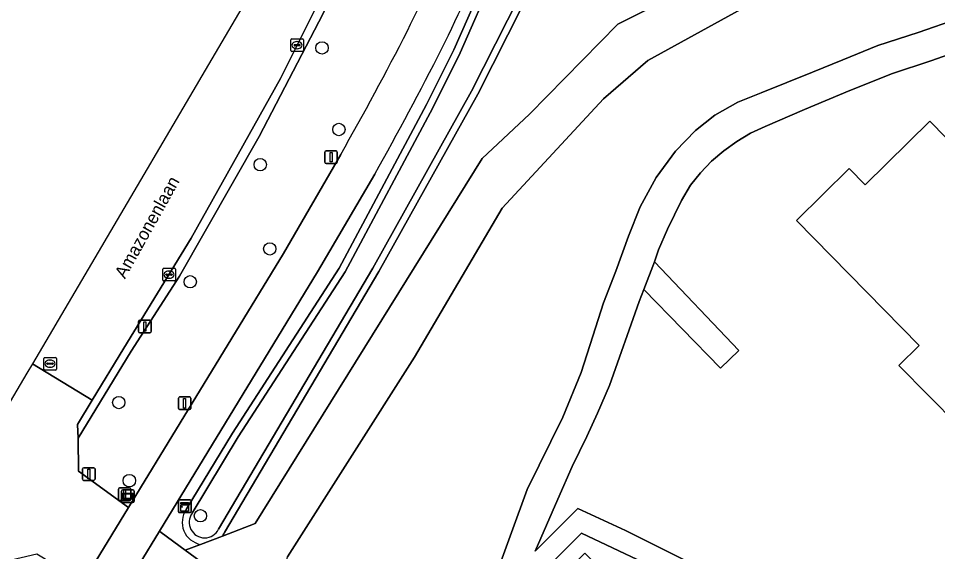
# Model space of a CAD drawing. Extents: x 162788 to 163838, y 385791 to 386523.
# Drawn here: x 162858.7 to 162931.3, y 386058.1 to 386100.2 of the extents above; entities that cross this region are included whole.
import ezdxf

# ---------------------------------------------------------------- set-up
doc = ezdxf.new("R2010")
doc.units = 0
for name, color, linetype in [('IMGEO_Boom', 7, 'Continuous'), ('IMGEO_Erf', 7, 'Continuous'), ('IMGEO_Fietspad_gesloten', 7, 'Continuous'), ('IMGEO_Groenvoorziening', 7, 'Continuous'), ('IMGEO_Kast', 7, 'Continuous'), ('IMGEO_Kolk', 7, 'Continuous'), ('IMGEO_Lichtmast', 7, 'Continuous'), ('IMGEO_Oever', 7, 'Continuous'), ('IMGEO_Openbare_ruimte_label', 7, 'Continuous'), ('IMGEO_Pand', 7, 'Continuous'), ('IMGEO_Rijbaan_lokaal_gesloten', 7, 'Continuous'), ('IMGEO_Rijbaan_lokaal_open', 7, 'Continuous'), ('IMGEO_Rioolput', 7, 'Continuous'), ('IMGEO_Verkeersbordpaal', 7, 'Continuous'), ('IMGEO_Voetpad_open', 7, 'Continuous'), ('IMGEO_Waterloop', 7, 'Continuous'), ('IMGEO_Wegwijzer', 7, 'Continuous'), ('IMGEO_Woonerf_gesloten', 7, 'Continuous'), ('IMGEO_Woonerf_open', 7, 'Continuous')]:
    doc.layers.add(name, color=color, linetype=linetype)

msp = doc.modelspace()

# ---------------------------------------------------------------- linework, layer by layer
at = {"layer": 'IMGEO_Boom'}
for centre in [(162882.663, 386097.882), (162883.994, 386091.44), (162877.776, 386088.662), (162878.536, 386082.008), (162872.249, 386079.408), (162866.6, 386069.865), (162867.433, 386063.695), (162873.051, 386060.918)]:
    msp.add_circle(centre, 0.489, dxfattribs=at)
at = {"layer": 'IMGEO_Erf'}
for points in [[(162934.439, 386098.157), (162930.777, 386096.853), (162927.751, 386095.851), (162924.39, 386094.51), (162920.807, 386093.021), (162917.678, 386091.681), (162916.531, 386091.144), (162915.438, 386090.504), (162914.409, 386089.765), (162913.452, 386088.935), (162912.576, 386088.02), (162911.788, 386087.028), (162911.062, 386085.833), (162909.961, 386083.574), (162909.245, 386081.939), (162908.938, 386080.983), (162915.594, 386073.987), (162914.145, 386072.584), (162908.085, 386078.794), (162907.738, 386077.852), (162905.396, 386071.212), (162904.448, 386069.029), (162903.588, 386067.177), (162902.433, 386064.802), (162901.305, 386062.228), (162899.512, 386058.136), (162902.875, 386061.502), (162906.638, 386059.762), (162914.557, 386055.812)], [(162932.93, 386068.048), (162928.259, 386072.8), (162929.852, 386074.366), (162920.15, 386084.237), (162924.336, 386088.352), (162925.591, 386087.076), (162930.69, 386092.088), (162939.722, 386082.898)]]:
    msp.add_lwpolyline(points, dxfattribs=at)
msp.add_lwpolyline([(162918.699, 386051.778), (162918.26, 386052.067), (162913.088, 386054.646), (162908.078, 386057.219), (162903.176, 386059.54), (162898.426, 386054.785), (162899.334, 386053.906), (162903.429, 386057.973), (162913.529, 386047.766), (162914.39, 386048.606), (162916.962, 386046.008), (162915.777, 386044.862), (162917.188, 386043.446), (162918.152, 386044.34), (162918.396, 386044.128), (162917.765, 386043.482), (162921.521, 386039.695), (162923.88, 386042.039), (162925.621, 386043.769), (162922.323, 386047.083), (162921.998, 386047.824), (162918.756, 386051.74)], close=True, dxfattribs=at)
at = {"layer": 'IMGEO_Fietspad_gesloten'}
for points in [[(162884.137, 386089.47), (162879.623, 386081.646), (162867.368, 386061.567), (162863.779, 386055.688), (162829.79, 386000), (162820.662, 385985.045)], [(162823.224, 385983.386), (162833.364, 386000), (162866.596, 386054.448), (162869.806, 386059.708), (162882.31, 386080.195), (162886.828, 386087.923)]]:
    msp.add_lwpolyline(points, dxfattribs=at)
for centre, radius, start, end in [((162659.063, 386209.733), 255.482, 334.37444, 338.57894), ((162717.543, 386184.554), 194.934, 333.58344, 339.20108), ((162670.339, 386211.28), 246.064, 330.32802, 332.91391), ((162683.634, 386202.903), 233.47, 330.49601, 333.2528)]:
    msp.add_arc(centre, radius, start, end, dxfattribs=at)
at = {"layer": 'IMGEO_Groenvoorziening'}
for points in [[(162871.933, 386061.417), (162875.581, 386067.445), (162884.024, 386080.479), (162890.922, 386093.403), (162893.07, 386097.727), (162895.786, 386103.895), (162905.141, 386127.836)], [(162907.863, 386125.267), (162899.723, 386103.62), (162894.974, 386094.22), (162887.154, 386080.222), (162874.965, 386059.593), (162874.913, 386059.498), (162874.855, 386059.406), (162874.791, 386059.317), (162877.368, 386060.296), (162895.333, 386089.156), (162899.073, 386092.639), (162906.04, 386099.773)], [(162906.04, 386099.773), (162912.338, 386102.938), (162924.209, 386109.405), (162925.052, 386112.426), (162934.709, 386117.77)], [(162938.78, 386111.247), (162928.686, 386105.678), (162925.793, 386106.483), (162908.415, 386096.881), (162904.907, 386093.859), (162896.908, 386085.212), (162889.984, 386073.464), (162879.935, 386057.678)], [(162884.918, 386105.052), (162883.213, 386101.598), (162882.742, 386100.615), (162877.694, 386090.889), (162871.409, 386079.854), (162867.572, 386073.915), (162863.384, 386067.049), (162863.415, 386064.433), (162867.368, 386061.567), (162879.623, 386081.646), (162884.137, 386089.47)], [(162896.29, 386055.904), (162898.872, 386062.985), (162901.706, 386068.713), (162903.136, 386072.245), (162904.079, 386075.111), (162904.913, 386077.744), (162905.897, 386080.251), (162906.885, 386083.002), (162907.811, 386085.338), (162909.061, 386087.648), (162910.59, 386089.723), (162912.191, 386091.347), (162913.7, 386092.561), (162915.522, 386093.594), (162917.363, 386094.344), (162921.428, 386095.97), (162923.82, 386096.946), (162926.598, 386098.081), (162929.787, 386099.112), (162932.958, 386100.213)], [(162886.828, 386087.923), (162882.31, 386080.195), (162869.806, 386059.708), (162869.96, 386059.595), (162871.857, 386058.203), (162873.055, 386058.658)]]:
    msp.add_lwpolyline(points, dxfattribs=at)
for centre, radius, start, end in [((162659.063, 386209.733), 255.482, 334.37444, 338.57894), ((162717.543, 386184.554), 194.934, 333.58344, 339.20108), ((162670.339, 386211.28), 246.064, 330.32802, 332.91391), ((162683.634, 386202.903), 233.47, 330.49601, 333.2528), ((162873.387, 386060.401), 1.774, 145.04131, 259.2188)]:
    msp.add_arc(centre, radius, start, end, dxfattribs=at)
at = {"layer": 'IMGEO_Kast'}
for p, q in [((162871.314, 386061.243), (162871.314, 386062.084)), ((162871.314, 386062.084), (162871.314, 386061.243)), ((162871.389, 386062.168), (162872.23, 386062.168)), ((162872.23, 386062.168), (162871.389, 386062.168)), ((162872.314, 386062.093), (162872.314, 386061.252)), ((162872.314, 386061.252), (162872.314, 386062.093)), ((162872.239, 386061.168), (162871.398, 386061.168)), ((162871.398, 386061.168), (162872.239, 386061.168))]:
    msp.add_line(p, q, dxfattribs=at)
for points in [[(162871.509, 386061.958), (162872.109, 386061.958), (162872.109, 386061.873), (162871.509, 386061.873), (162871.509, 386061.958)], [(162871.509, 386061.783), (162872.109, 386061.783), (162872.109, 386061.294), (162871.509, 386061.294), (162871.509, 386061.783)]]:
    msp.add_lwpolyline(points, dxfattribs=at)
msp.add_circle((162871.593, 386061.632), 0.0377, dxfattribs=at)
for centre, start, end in [((162871.392, 386062.09), 92.4484, 184.28452), ((162871.392, 386062.09), 92.4484, 184.28452), ((162872.236, 386062.09), 2.4484, 94.28452), ((162872.236, 386062.09), 2.4484, 94.28452), ((162871.392, 386061.246), 182.4484, 274.28452), ((162871.392, 386061.246), 182.4484, 274.28452), ((162872.236, 386061.246), 272.4484, 4.28452), ((162872.236, 386061.246), 272.4484, 4.28452)]:
    msp.add_arc(centre, 0.0779, start, end, dxfattribs=at)
at = {"layer": 'IMGEO_Kolk'}
for p, q in [((162880.19, 386097.678), (162880.19, 386098.53)), ((162880.265, 386098.604), (162881.117, 386098.604)), ((162880.678, 386098.384), (162880.703, 386098.384)), ((162881.191, 386098.53), (162881.191, 386097.678)), ((162880.449, 386098.098), (162880.449, 386098.11)), ((162880.887, 386098.061), (162880.489, 386098.061)), ((162880.492, 386098.147), (162880.89, 386098.147)), ((162880.701, 386097.824), (162880.676, 386097.824)), ((162880.933, 386098.11), (162880.933, 386098.098)), ((162881.117, 386097.604), (162880.265, 386097.604)), ((162870.072, 386079.544), (162870.072, 386080.396)), ((162870.147, 386080.47), (162870.999, 386080.47)), ((162870.56, 386080.25), (162870.585, 386080.25)), ((162871.073, 386080.396), (162871.073, 386079.544)), ((162870.999, 386079.47), (162870.147, 386079.47)), ((162870.331, 386079.964), (162870.331, 386079.976)), ((162870.769, 386079.927), (162870.371, 386079.927)), ((162870.374, 386080.013), (162870.772, 386080.013)), ((162870.583, 386079.69), (162870.558, 386079.69)), ((162870.815, 386079.976), (162870.815, 386079.964))]:
    msp.add_line(p, q, dxfattribs=at)
for points in [[(162880.19, 386097.678), (162880.19, 386098.53)], [(162880.265, 386098.604), (162881.117, 386098.604)], [(162881.191, 386098.53), (162881.191, 386097.678)], [(162881.117, 386097.604), (162880.265, 386097.604)], [(162870.072, 386079.544), (162870.072, 386080.396)], [(162870.147, 386080.47), (162870.999, 386080.47)], [(162871.073, 386080.396), (162871.073, 386079.544)], [(162870.999, 386079.47), (162870.147, 386079.47)]]:
    msp.add_lwpolyline(points, dxfattribs=at)
for centre, radius, start, end in [((162880.267, 386098.528), 0.0765, 91.55205, 178.44795), ((162880.267, 386098.528), 0.0765, 91.55205, 178.44795), ((162881.115, 386098.528), 0.0765, 1.55205, 88.44795), ((162881.115, 386098.528), 0.0765, 1.55205, 88.44795), ((162880.267, 386097.68), 0.0765, 181.55205, 268.44795), ((162880.267, 386097.68), 0.0765, 181.55205, 268.44795), ((162880.489, 386098.107), 0.0403, 85.87752, 175.75265), ((162880.486, 386098.097), 0.0366, 178.93798, 274.71019), ((162880.89, 386098.104), 0.043, 264.86636, 352.45326), ((162880.894, 386098.109), 0.0386, 1.73085, 96.63898), ((162881.115, 386097.68), 0.0765, 271.55205, 358.44795), ((162881.115, 386097.68), 0.0765, 271.55205, 358.44795), ((162870.149, 386080.394), 0.0765, 91.55205, 178.44795), ((162870.149, 386080.394), 0.0765, 91.55205, 178.44795), ((162870.997, 386080.394), 0.0765, 1.55205, 88.44795), ((162870.997, 386080.394), 0.0765, 1.55205, 88.44795), ((162870.149, 386079.546), 0.0765, 181.55205, 268.44795), ((162870.149, 386079.546), 0.0765, 181.55205, 268.44795), ((162870.371, 386079.973), 0.0403, 85.87752, 175.75265), ((162870.368, 386079.963), 0.0366, 178.93798, 274.71019), ((162870.772, 386079.97), 0.043, 264.86636, 352.45326), ((162870.776, 386079.975), 0.0386, 1.73085, 96.63898), ((162870.997, 386079.546), 0.0765, 271.55205, 358.44795), ((162870.997, 386079.546), 0.0765, 271.55205, 358.44795)]:
    msp.add_arc(centre, radius, start, end, dxfattribs=at)
for centre, major_axis, ratio, start_param, end_param in [((162880.677, 386098.104), (-0.387, 0.002), 0.722429, 4.712389, 7.853982), ((162880.702, 386098.104), (-0.39, 0.002), 0.717154, 1.570796, 4.712389), ((162870.559, 386079.97), (-0.387, 0.002), 0.722429, 4.712389, 7.853982), ((162870.584, 386079.97), (-0.39, 0.002), 0.717154, 1.570796, 4.712389)]:
    msp.add_ellipse(centre, major_axis=major_axis, ratio=ratio, start_param=start_param, end_param=end_param, dxfattribs=at)
at = {"layer": 'IMGEO_Lichtmast'}
for p, q in [((162882.883, 386088.85), (162882.883, 386089.65)), ((162882.883, 386089.65), (162882.883, 386088.85)), ((162882.983, 386089.75), (162883.773, 386089.75)), ((162883.773, 386089.75), (162882.983, 386089.75)), ((162883.873, 386089.65), (162883.873, 386088.85)), ((162883.873, 386088.85), (162883.873, 386089.65)), ((162883.773, 386088.75), (162882.983, 386088.75)), ((162882.983, 386088.75), (162883.773, 386088.75)), ((162868.166, 386075.475), (162868.166, 386076.275)), ((162868.166, 386076.275), (162868.166, 386075.475)), ((162868.266, 386076.375), (162869.056, 386076.375)), ((162869.056, 386076.375), (162868.266, 386076.375)), ((162869.156, 386076.275), (162869.156, 386075.475)), ((162869.156, 386075.475), (162869.156, 386076.275)), ((162869.056, 386075.375), (162868.266, 386075.375)), ((162868.266, 386075.375), (162869.056, 386075.375)), ((162871.308, 386069.405), (162871.308, 386070.205)), ((162871.308, 386070.205), (162871.308, 386069.405)), ((162871.408, 386070.305), (162872.198, 386070.305)), ((162872.198, 386070.305), (162871.408, 386070.305)), ((162872.298, 386070.205), (162872.298, 386069.405)), ((162872.298, 386069.405), (162872.298, 386070.205)), ((162872.198, 386069.305), (162871.408, 386069.305)), ((162871.408, 386069.305), (162872.198, 386069.305))]:
    msp.add_line(p, q, dxfattribs=at)
for points in [[(162883.303, 386089.625), (162883.453, 386089.625), (162883.453, 386088.875), (162883.303, 386088.875), (162883.303, 386089.625)], [(162868.586, 386076.25), (162868.736, 386076.25), (162868.736, 386075.5), (162868.586, 386075.5), (162868.586, 386076.25)], [(162871.728, 386070.18), (162871.878, 386070.18), (162871.878, 386069.43), (162871.728, 386069.43), (162871.728, 386070.18)]]:
    msp.add_lwpolyline(points, dxfattribs=at)
for centre, start, end in [((162882.983, 386089.65), 90, 180), ((162882.983, 386089.65), 90, 180), ((162883.773, 386089.65), 0, 90), ((162883.773, 386089.65), 360, 90), ((162882.983, 386088.85), 180, 270), ((162882.983, 386088.85), 180, 270), ((162883.773, 386088.85), 270, 0), ((162883.773, 386088.85), 270, 0), ((162868.266, 386076.275), 90, 180), ((162868.266, 386076.275), 90, 180), ((162869.056, 386076.275), 0, 90), ((162869.056, 386076.275), 360, 90), ((162868.266, 386075.475), 180, 270), ((162868.266, 386075.475), 180, 270), ((162869.056, 386075.475), 270, 0), ((162869.056, 386075.475), 270, 0), ((162871.408, 386070.205), 90, 180), ((162871.408, 386070.205), 90, 180), ((162872.198, 386070.205), 0, 90), ((162872.198, 386070.205), 360, 90), ((162871.408, 386069.405), 180, 270), ((162871.408, 386069.405), 180, 270), ((162872.198, 386069.405), 270, 0), ((162872.198, 386069.405), 270, 0)]:
    msp.add_arc(centre, 0.1, start, end, dxfattribs=at)
at = {"layer": 'IMGEO_Oever'}
for points in [[(162905.141, 386127.836), (162895.786, 386103.895), (162893.07, 386097.727), (162890.922, 386093.403), (162884.024, 386080.479), (162875.581, 386067.445), (162871.933, 386061.417)], [(162872.393, 386061.115), (162876.047, 386067.153), (162884.498, 386080.2), (162891.411, 386093.151), (162893.568, 386097.494), (162896.294, 386103.684), (162905.643, 386127.61)], [(162873.055, 386058.658), (162874.791, 386059.317), (162874.855, 386059.406), (162874.913, 386059.498), (162874.965, 386059.593), (162887.154, 386080.222), (162894.974, 386094.22), (162899.723, 386103.62), (162907.863, 386125.267)], [(162907.344, 386125.448), (162899.219, 386103.841), (162894.489, 386094.478), (162886.678, 386080.496), (162874.483, 386059.857)]]:
    msp.add_lwpolyline(points, dxfattribs=at)
for centre, radius, start, end in [((162873.387, 386060.401), 1.774, 145.04131, 259.2188), ((162873.386, 386060.4), 1.224, 144.23135, 333.68001)]:
    msp.add_arc(centre, radius, start, end, dxfattribs=at)
at = {"layer": 'IMGEO_Pand'}
msp.add_lwpolyline([(162939.722, 386082.898), (162930.69, 386092.088), (162925.591, 386087.076), (162924.336, 386088.352), (162920.15, 386084.237), (162929.852, 386074.366), (162928.259, 386072.8), (162932.93, 386068.048)], dxfattribs=at)
at = {"layer": 'IMGEO_Rijbaan_lokaal_gesloten'}
for points in [[(162903.689, 386185.187), (162903.856, 386192.516), (162903.885, 386193.067), (162903.829, 386200.635), (162899.537, 386200.494), (162898.536, 386185.264), (162896.308, 386162.558), (162890.521, 386135.54), (162878.624, 386104.983), (162859.772, 386072.924)], [(162859.772, 386072.924), (162859.772, 386072.924), (162864.499, 386070.058), (162866.989, 386074.154), (162872.319, 386082.845), (162879.372, 386095.475), (162881.82, 386100.356), (162882.465, 386101.636), (162886.236, 386110.011)]]:
    msp.add_lwpolyline(points, dxfattribs=at)
at = {"layer": 'IMGEO_Rijbaan_lokaal_open'}
msp.add_lwpolyline([(162850.366, 386057.018), (162850.366, 386057.018), (162854.836, 386054.201), (162856.636, 386057.112), (162857.378, 386057.283), (162857.65, 386057.346), (162860.126, 386057.918), (162863.779, 386055.688), (162867.368, 386061.567), (162863.415, 386064.433), (162863.384, 386067.049), (162863.345, 386068.122), (162864.499, 386070.058), (162859.772, 386072.924), (162859.772, 386072.924), (162859.331, 386072.175)], close=True, dxfattribs=at)
at = {"layer": 'IMGEO_Rioolput'}
for p, q in [((162860.667, 386072.506), (162860.667, 386073.358)), ((162860.742, 386073.432), (162861.594, 386073.432)), ((162860.926, 386072.926), (162860.926, 386072.938)), ((162860.969, 386072.975), (162861.367, 386072.975)), ((162861.155, 386073.212), (162861.18, 386073.212)), ((162861.41, 386072.938), (162861.41, 386072.926)), ((162861.668, 386073.358), (162861.668, 386072.506)), ((162861.594, 386072.432), (162860.742, 386072.432)), ((162861.364, 386072.889), (162860.966, 386072.889)), ((162861.178, 386072.652), (162861.153, 386072.652))]:
    msp.add_line(p, q, dxfattribs=at)
for points in [[(162860.667, 386072.506), (162860.667, 386073.358)], [(162860.742, 386073.432), (162861.594, 386073.432)], [(162861.668, 386073.358), (162861.668, 386072.506)], [(162861.594, 386072.432), (162860.742, 386072.432)]]:
    msp.add_lwpolyline(points, dxfattribs=at)
for centre, radius, start, end in [((162860.744, 386073.356), 0.0765, 91.55205, 178.44795), ((162860.744, 386073.356), 0.0765, 91.55205, 178.44795), ((162860.966, 386072.935), 0.0403, 85.87752, 175.75265), ((162860.963, 386072.925), 0.0366, 178.93798, 274.71019), ((162861.367, 386072.932), 0.043, 264.86636, 352.45326), ((162861.371, 386072.937), 0.0386, 1.73085, 96.63898), ((162861.592, 386073.356), 0.0765, 1.55205, 88.44795), ((162861.592, 386073.356), 0.0765, 1.55205, 88.44795), ((162860.744, 386072.508), 0.0765, 181.55205, 268.44795), ((162860.744, 386072.508), 0.0765, 181.55205, 268.44795), ((162861.592, 386072.508), 0.0765, 271.55205, 358.44795), ((162861.592, 386072.508), 0.0765, 271.55205, 358.44795)]:
    msp.add_arc(centre, radius, start, end, dxfattribs=at)
for centre, major_axis, ratio, start_param, end_param in [((162861.154, 386072.932), (-0.387, 0.002), 0.722429, 4.712389, 7.853982), ((162861.179, 386072.932), (-0.39, 0.002), 0.717154, 1.570796, 4.712389)]:
    msp.add_ellipse(centre, major_axis=major_axis, ratio=ratio, start_param=start_param, end_param=end_param, dxfattribs=at)
at = {"layer": 'IMGEO_Verkeersbordpaal'}
for p, q in [((162863.731, 386063.817), (162863.731, 386064.617)), ((162863.731, 386064.617), (162863.731, 386063.817)), ((162863.831, 386064.717), (162864.621, 386064.717)), ((162864.621, 386064.717), (162863.831, 386064.717)), ((162864.721, 386064.617), (162864.721, 386063.817)), ((162864.721, 386063.817), (162864.721, 386064.617)), ((162864.621, 386063.717), (162863.831, 386063.717)), ((162863.831, 386063.717), (162864.621, 386063.717)), ((162866.569, 386062.229), (162866.569, 386063.029)), ((162866.569, 386063.029), (162866.569, 386062.229)), ((162866.669, 386063.129), (162867.459, 386063.129)), ((162867.459, 386063.129), (162866.669, 386063.129)), ((162867.559, 386063.029), (162867.559, 386062.229)), ((162867.559, 386062.229), (162867.559, 386063.029)), ((162867.459, 386062.129), (162866.669, 386062.129)), ((162866.669, 386062.129), (162867.459, 386062.129))]:
    msp.add_line(p, q, dxfattribs=at)
for points in [[(162864.151, 386064.592), (162864.301, 386064.592), (162864.301, 386063.842), (162864.151, 386063.842), (162864.151, 386064.592)], [(162866.989, 386063.004), (162867.139, 386063.004), (162867.139, 386062.254), (162866.989, 386062.254), (162866.989, 386063.004)]]:
    msp.add_lwpolyline(points, dxfattribs=at)
for centre, start, end in [((162863.831, 386064.617), 90, 180), ((162863.831, 386064.617), 90, 180), ((162864.621, 386064.617), 0, 90), ((162864.621, 386064.617), 360, 90), ((162863.831, 386063.817), 180, 270), ((162863.831, 386063.817), 180, 270), ((162864.621, 386063.817), 270, 0), ((162864.621, 386063.817), 270, 0), ((162866.669, 386063.029), 90, 180), ((162866.669, 386063.029), 90, 180), ((162867.459, 386063.029), 0, 90), ((162867.459, 386063.029), 360, 90), ((162866.669, 386062.229), 180, 270), ((162866.669, 386062.229), 180, 270), ((162867.459, 386062.229), 270, 0), ((162867.459, 386062.229), 270, 0)]:
    msp.add_arc(centre, 0.1, start, end, dxfattribs=at)
at = {"layer": 'IMGEO_Voetpad_open'}
msp.add_lwpolyline([(162886.236, 386110.011), (162882.465, 386101.636), (162881.82, 386100.356), (162879.372, 386095.475), (162872.319, 386082.845), (162866.989, 386074.154), (162864.499, 386070.058), (162863.345, 386068.122), (162863.384, 386067.049), (162867.572, 386073.915), (162871.409, 386079.854), (162877.694, 386090.889), (162882.742, 386100.615), (162883.213, 386101.598), (162884.918, 386105.052)], dxfattribs=at)
msp.add_lwpolyline([(162908.938, 386080.983), (162908.085, 386078.794), (162914.145, 386072.584), (162915.594, 386073.987)], close=True, dxfattribs=at)
at = {"layer": 'IMGEO_Waterloop'}
for points in [[(162905.643, 386127.61), (162896.294, 386103.684), (162893.568, 386097.494), (162891.411, 386093.151), (162884.498, 386080.2), (162876.047, 386067.153), (162872.393, 386061.115)], [(162894.489, 386094.478), (162899.219, 386103.841), (162907.344, 386125.448)], [(162874.483, 386059.857), (162886.678, 386080.496), (162894.489, 386094.478)]]:
    msp.add_lwpolyline(points, dxfattribs=at)
msp.add_arc((162873.386, 386060.4), 1.224, 144.23135, 333.68001, dxfattribs=at)
at = {"layer": 'IMGEO_Wegwijzer'}
for p, q in [((162866.823, 386062.069), (162866.823, 386062.869)), ((162866.823, 386062.869), (162866.823, 386062.069)), ((162866.923, 386062.969), (162867.713, 386062.969)), ((162867.713, 386062.969), (162866.923, 386062.969)), ((162867.813, 386062.869), (162867.813, 386062.069)), ((162867.813, 386062.069), (162867.813, 386062.869)), ((162867.713, 386061.969), (162866.923, 386061.969)), ((162866.923, 386061.969), (162867.713, 386061.969))]:
    msp.add_line(p, q, dxfattribs=at)
for points in [[(162866.924, 386062.701), (162867.712, 386062.701), (162867.712, 386062.237), (162866.924, 386062.237), (162866.924, 386062.701)], [(162866.989, 386062.636), (162866.989, 386062.302), (162867.647, 386062.302), (162867.647, 386062.636), (162866.989, 386062.636)]]:
    msp.add_lwpolyline(points, dxfattribs=at)
for centre, start, end in [((162866.923, 386062.869), 90, 180), ((162866.923, 386062.869), 90, 180), ((162867.713, 386062.869), 0, 90), ((162867.713, 386062.869), 360, 90), ((162866.923, 386062.069), 180, 270), ((162866.923, 386062.069), 180, 270), ((162867.713, 386062.069), 270, 0), ((162867.713, 386062.069), 270, 0)]:
    msp.add_arc(centre, 0.1, start, end, dxfattribs=at)
at = {"layer": 'IMGEO_Woonerf_gesloten'}
for points in [[(162932.958, 386100.213), (162929.787, 386099.112), (162926.598, 386098.081), (162923.82, 386096.946), (162921.428, 386095.97), (162917.363, 386094.344), (162915.522, 386093.594), (162913.7, 386092.561), (162912.191, 386091.347), (162910.59, 386089.723), (162909.061, 386087.648), (162907.811, 386085.338), (162906.885, 386083.002), (162905.897, 386080.251), (162904.913, 386077.744), (162904.079, 386075.111), (162903.136, 386072.245), (162901.706, 386068.713), (162898.872, 386062.985), (162896.29, 386055.904)], [(162914.557, 386055.812), (162906.638, 386059.762), (162902.875, 386061.502), (162899.512, 386058.136), (162901.305, 386062.228), (162902.433, 386064.802), (162903.588, 386067.177), (162904.448, 386069.029), (162905.396, 386071.212), (162907.738, 386077.852), (162908.085, 386078.794), (162908.938, 386080.983), (162909.245, 386081.939), (162909.961, 386083.574), (162911.062, 386085.833), (162911.788, 386087.028), (162912.576, 386088.02), (162913.452, 386088.935), (162914.409, 386089.765), (162915.438, 386090.504), (162916.531, 386091.144), (162917.678, 386091.681), (162920.807, 386093.021), (162924.39, 386094.51), (162927.751, 386095.851), (162930.777, 386096.853), (162934.439, 386098.157)], [(162888.584, 386044.934), (162887.245, 386046.272), (162884.857, 386048.66), (162878.872, 386053.053), (162871.857, 386058.203), (162869.96, 386059.595), (162869.806, 386059.708), (162866.596, 386054.448), (162866.736, 386054.36), (162879.618, 386046.265), (162882.138, 386044.34), (162888.045, 386038.43), (162926.458, 386000), (162929.048, 385997.409)], [(162898.426, 386054.785), (162903.176, 386059.54), (162908.078, 386057.219)]]:
    msp.add_lwpolyline(points, dxfattribs=at)
at = {"layer": 'IMGEO_Woonerf_open'}
msp.add_lwpolyline([(162937.968, 386116.9), (162924.209, 386109.405), (162912.338, 386102.938), (162906.04, 386099.773), (162899.073, 386092.639), (162895.333, 386089.156), (162877.368, 386060.296), (162874.791, 386059.317), (162873.055, 386058.658), (162871.857, 386058.203), (162878.872, 386053.053), (162879.935, 386057.678), (162889.984, 386073.464), (162896.908, 386085.212), (162904.907, 386093.859), (162908.415, 386096.881), (162925.793, 386106.483), (162939.45, 386114.029)], dxfattribs=at)

# ---------------------------------------------------------------- texts
at = {"layer": 'IMGEO_Openbare_ruimte_label'}
msp.add_text('Amazonenlaan', height=1, rotation=60.79516, dxfattribs=at).set_placement((162867.088, 386079.585))

doc.saveas('drawing.dxf')
